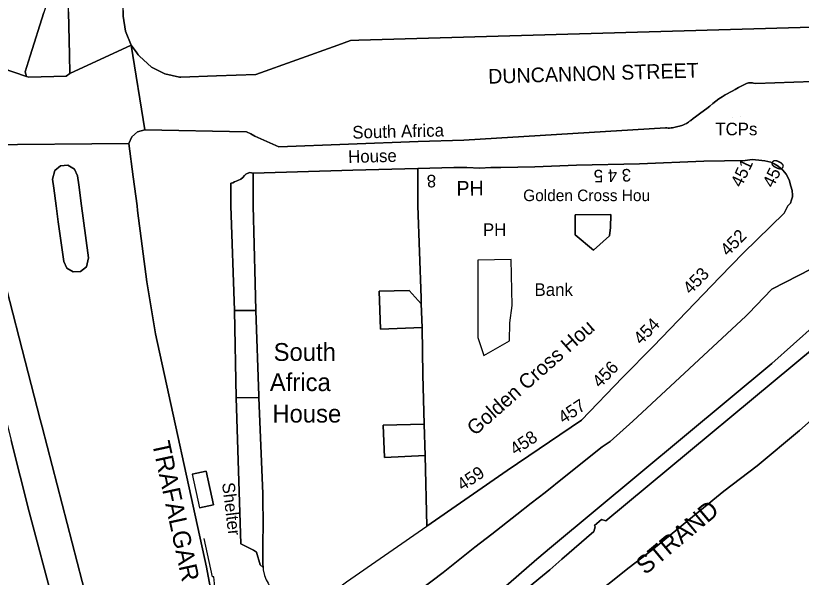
# Model space of a CAD drawing. Extents: x 529240 to 530363, y 179600 to 180767.
# Drawn here: x 530056.2 to 530149.8, y 180455.7 to 180522.7 of the extents above; entities that cross this region are included whole.
import ezdxf

# ---------------------------------------------------------------- set-up
doc = ezdxf.new("R2010")
doc.units = 0
for name, color, linetype in [('Building', 7, 'Continuous'), ('General surface', 7, 'Continuous'), ('Road Or Track', 7, 'Continuous'), ('Roadside', 7, 'Continuous'), ('Structure', 7, 'Continuous'), ('Unclassified', 7, 'Continuous')]:
    doc.layers.add(name, color=color, linetype=linetype)

msp = doc.modelspace()

# ---------------------------------------------------------------- linework, layer by layer
at = {"layer": 'Building'}
for points in [[(530105.2, 180461.8), (530114.8, 180468.45), (530123.65, 180474.45), (530128.55, 180479.5), (530132.25, 180483.25), (530140.15, 180491.5), (530142.95, 180494.4), (530147.8, 180499.1), (530148.25, 180500), (530148.55, 180500.3), (530148.7, 180500.7), (530148.8, 180501.05), (530148.8, 180501.25), (530148.75, 180501.8), (530148.6, 180502.35), (530148.4, 180503.1), (530148.05, 180503.75), (530147.65, 180504.25), (530147.1, 180504.7), (530146.6, 180505), (530146.2, 180505.2), (530145.5, 180505.35), (530144.8, 180505.45), (530144, 180505.5), (530143.15, 180505.4), (530138.25, 180505.3), (530130.55, 180505), (530123.05, 180504.85), (530118.1, 180504.65), (530114.05, 180504.55), (530112.85, 180504.55), (530111.55, 180504.5), (530110, 180504.55), (530108.45, 180504.55), (530104.15, 180504.45), (530104.15, 180500), (530104.55, 180489), (530104.55, 180488.3), (530104.65, 180485.5), (530104.75, 180479.85), (530104.9, 180473.95), (530105, 180470.2)], [(530125.1, 180494.7), (530127, 180496.4), (530127.1, 180497.4), (530127.15, 180498.95), (530122.9, 180498.9), (530122.9, 180496.55)], [(530112, 180482.15), (530115.05, 180483.9), (530115.1, 180486.05), (530115.4, 180488.1), (530115.25, 180493.6), (530111.3, 180493.5), (530111.3, 180484.3)], [(530082.3, 180487.5), (530082.5, 180477.1), (530085.2, 180477.15), (530085.2, 180477.35), (530084.85, 180487.5)], [(530078.11, 180463.98), (530079.77, 180464.34), (530078.9, 180468.34), (530077.24, 180467.98)]]:
    msp.add_lwpolyline(points, close=True, dxfattribs=at)
for points in [[(530104.15, 180504.45), (530108.45, 180504.55), (530110, 180504.55), (530111.55, 180504.5), (530112.85, 180504.55), (530114.05, 180504.55), (530118.1, 180504.65), (530123.05, 180504.85), (530130.55, 180505), (530138.25, 180505.3)], [(530138.25, 180505.3), (530143.15, 180505.4), (530144, 180505.5), (530144.8, 180505.45), (530145.5, 180505.35), (530146.2, 180505.2), (530146.6, 180505), (530147.1, 180504.7), (530147.65, 180504.25), (530148.05, 180503.75), (530148.4, 180503.1), (530148.6, 180502.35), (530148.75, 180501.8), (530148.8, 180501.25), (530148.8, 180501.05), (530148.7, 180500.7), (530148.55, 180500.3), (530148.25, 180500), (530147.8, 180499.1), (530142.95, 180494.4), (530140.15, 180491.5), (530132.25, 180483.25), (530128.55, 180479.5), (530123.65, 180474.45), (530114.8, 180468.45), (530105.2, 180461.8)], [(530095.65, 180455.15), (530105.2, 180461.8), (530105, 180470.2), (530100.15, 180470), (530100, 180473.85), (530104.9, 180473.95), (530104.75, 180479.85), (530104.65, 180485.5), (530099.7, 180485.3), (530099.55, 180489.8), (530103.1, 180489.9), (530104.55, 180488.3), (530104.55, 180489), (530104.15, 180500), (530104.15, 180504.45), (530096.4, 180504.25), (530084.5, 180503.9), (530084.5, 180500), (530084.75, 180490.75), (530084.85, 180487.5), (530085.2, 180477.35), (530085.2, 180477.15), (530085.65, 180465.65), (530085.7, 180461.5), (530085.65, 180460.25), (530085.65, 180457.3), (530085.7, 180456.85), (530085.7, 180456.6), (530085.85, 180455.9), (530086.05, 180455.4)], [(530084.5, 180503.9), (530096.4, 180504.25), (530104.15, 180504.45)], [(530104.15, 180504.45), (530104.15, 180500), (530104.55, 180489), (530104.55, 180488.3)], [(530084.85, 180487.5), (530084.75, 180490.75), (530084.5, 180500), (530084.5, 180503.9)], [(530127, 180496.4), (530125.1, 180494.7), (530122.9, 180496.55), (530122.9, 180498.9), (530127.15, 180498.95), (530127.1, 180497.4), (530127, 180496.4)], [(530112, 180482.15), (530115.05, 180483.9), (530115.1, 180486.05), (530115.4, 180488.1), (530115.25, 180493.6), (530111.3, 180493.5), (530111.3, 180484.3), (530112, 180482.15)], [(530104.65, 180485.5), (530099.7, 180485.3), (530099.55, 180489.8), (530103.1, 180489.9), (530104.55, 180488.3)], [(530084.85, 180487.5), (530085.2, 180477.35), (530085.2, 180477.15)], [(530104.55, 180488.3), (530104.65, 180485.5)], [(530104.65, 180485.5), (530104.75, 180479.85), (530104.9, 180473.95)], [(530085.2, 180477.15), (530085.65, 180465.65), (530085.7, 180461.5), (530085.65, 180460.25), (530085.65, 180457.3), (530085.7, 180456.85)], [(530105, 180470.2), (530100.15, 180470), (530100, 180473.85), (530104.9, 180473.95)], [(530104.9, 180473.95), (530105, 180470.2)], [(530105, 180470.2), (530105.2, 180461.8)], [(530085.7, 180456.85), (530085.7, 180456.6), (530085.85, 180455.9), (530086.05, 180455.4), (530086.3, 180455), (530086.45, 180454.65), (530086.75, 180454.2), (530087.25, 180453.6), (530087.65, 180453.25), (530088.05, 180453), (530088.45, 180452.8), (530088.8, 180452.65), (530089.05, 180452.65), (530089.45, 180452.45), (530090.2, 180452.55), (530090.95, 180452.7), (530092.15, 180453), (530092.7, 180453.15), (530093.3, 180453.4), (530095.65, 180455.15), (530105.2, 180461.8)]]:
    msp.add_lwpolyline(points, dxfattribs=at)
at = {"layer": 'General surface'}
for points in [[(530084.5, 180503.9), (530084.1, 180503.95), (530083.8, 180503.85), (530083.65, 180503.75), (530083.5, 180503.6), (530083.3, 180503.35), (530083.05, 180503.15), (530082.7, 180503), (530082.3, 180502.85), (530082.1, 180502.75), (530081.85, 180502.7), (530081.85, 180500), (530082.3, 180487.5), (530084.85, 180487.5), (530084.75, 180490.75), (530084.5, 180500)], [(530127, 180496.4), (530127.1, 180497.4), (530127.15, 180498.95), (530122.9, 180498.9), (530122.9, 180496.55), (530125.1, 180494.7)], [(530112, 180482.15), (530115.05, 180483.9), (530115.1, 180486.05), (530115.4, 180488.1), (530115.25, 180493.6), (530111.3, 180493.5), (530111.3, 180484.3)], [(530104.65, 180485.5), (530104.55, 180488.3), (530103.1, 180489.9), (530099.55, 180489.8), (530099.7, 180485.3)], [(530082.5, 180477.1), (530083.05, 180459.7), (530084.55, 180458.95), (530084.9, 180458.7), (530085.35, 180457.2), (530085.7, 180456.85), (530085.65, 180457.3), (530085.65, 180460.25), (530085.7, 180461.5), (530085.65, 180465.65), (530085.2, 180477.15)], [(530104.9, 180473.95), (530100, 180473.85), (530100.15, 180470), (530105, 180470.2)]]:
    msp.add_lwpolyline(points, close=True, dxfattribs=at)
msp.add_lwpolyline([(530060.7, 180452.6), (530057.8, 180463.5), (530055.65, 180472)], dxfattribs=at)
at = {"layer": 'Road Or Track'}
for points in [[(530069.97, 180519.15), (530069.29, 180520.82), (530069.03, 180522.59), (530069.01, 180523.29), (530068.01, 180558.74), (530068.48, 180559.06), (530070.58, 180559.07), (530070.57, 180570.77), (530067.21, 180570.76), (530066.84, 180570.93), (530065.39, 180579.19), (530063.66, 180587.1), (530063.26, 180588.57), (530062.26, 180592.29), (530061.55, 180594.92), (530058.96, 180602.86)], [(530062.67, 180515.77), (530062.62, 180518.01), (530062.5, 180523.11), (530062.44, 180525.64), (530062.25, 180526.2), (530061.78, 180526.56), (530061.19, 180526.59), (530060.69, 180526.27), (530060.49, 180525.92), (530059.57, 180523.04), (530057.93, 180517.89), (530057.32, 180515.98), (530057.48, 180515.43)], [(530053.15, 180516.9), (530057.48, 180515.43), (530057.32, 180515.98), (530057.93, 180517.89), (530059.57, 180523.04)], [(530062.5, 180523.11), (530062.62, 180518.01), (530062.67, 180515.77), (530069.97, 180519.15), (530069.29, 180520.82), (530069.03, 180522.59), (530069.01, 180523.29)], [(530174.99, 180522.51), (530174.16, 180522.33), (530173.08, 180522.14), (530172, 180522), (530169.9, 180522), (530169.13, 180521.97), (530151.1, 180521.3), (530097.11, 180519.73), (530096.11, 180519.69), (530094.62, 180519.16), (530084.85, 180515.65), (530080.13, 180515.48), (530075.9, 180515.34), (530075.74, 180515.33), (530073.99, 180515.73), (530072.39, 180516.54), (530070.95, 180517.85), (530070.8, 180518), (530070.64, 180518.22), (530070.43, 180518.52), (530069.97, 180519.15)], [(530151.1, 180521.3), (530097.11, 180519.73), (530096.11, 180519.69), (530094.62, 180519.16), (530084.85, 180515.65), (530080.13, 180515.48), (530075.9, 180515.34), (530075.74, 180515.33), (530073.99, 180515.73), (530072.39, 180516.54), (530070.95, 180517.85), (530070.8, 180518), (530070.64, 180518.22), (530070.43, 180518.52), (530069.97, 180519.15), (530071.6, 180509.06), (530083.71, 180508.81), (530084.24, 180508.57), (530084.71, 180508.31), (530087.59, 180507.02), (530104.2, 180507.65), (530109.61, 180507.83), (530133.65, 180509.29), (530133.81, 180509.28), (530133.98, 180509.27), (530134.15, 180509.27), (530134.32, 180509.28), (530134.49, 180509.3), (530134.65, 180509.32), (530134.82, 180509.35), (530134.99, 180509.39), (530135.15, 180509.43), (530135.32, 180509.48), (530135.74, 180509.62), (530135.95, 180509.71), (530136.15, 180509.81), (530136.29, 180509.89), (530136.42, 180509.98), (530136.54, 180510.07), (530136.67, 180510.16), (530136.95, 180510.39), (530137.24, 180510.61), (530137.89, 180511.07), (530138.6, 180511.59), (530138.95, 180511.89), (530139.3, 180512.18), (530139.66, 180512.47), (530140.02, 180512.75), (530140.4, 180513), (530140.79, 180513.24), (530141.59, 180513.66), (530141.98, 180513.88), (530142.38, 180514.08), (530143.33, 180514.57), (530143.44, 180514.61), (530143.56, 180514.64), (530143.8, 180514.66), (530144.04, 180514.64), (530144.17, 180514.62), (530144.41, 180514.58), (530155.75, 180514.98)], [(530057.48, 180515.43), (530057.79, 180515.32), (530062.21, 180515.44), (530062.67, 180515.77)], [(530071.6, 180509.06), (530083.71, 180508.81), (530084.24, 180508.57), (530084.71, 180508.31), (530087.59, 180507.02), (530104.2, 180507.65), (530109.61, 180507.83), (530133.65, 180509.29), (530133.81, 180509.28), (530133.98, 180509.27), (530134.15, 180509.27), (530134.32, 180509.28), (530134.49, 180509.3), (530134.65, 180509.32), (530134.82, 180509.35), (530134.99, 180509.39), (530135.15, 180509.43), (530135.32, 180509.48), (530135.74, 180509.62), (530135.95, 180509.71), (530136.15, 180509.81), (530136.29, 180509.89), (530136.42, 180509.98), (530136.54, 180510.07), (530136.67, 180510.16), (530136.95, 180510.39), (530137.24, 180510.61), (530137.89, 180511.07), (530138.6, 180511.59), (530138.95, 180511.89), (530139.3, 180512.18), (530139.66, 180512.47), (530140.02, 180512.75), (530140.4, 180513), (530140.79, 180513.24), (530141.59, 180513.66), (530141.98, 180513.88), (530142.38, 180514.08), (530143.33, 180514.57), (530143.44, 180514.61), (530143.56, 180514.64), (530143.8, 180514.66), (530144.04, 180514.64), (530144.17, 180514.62), (530144.41, 180514.58), (530155.75, 180514.98)], [(530069.71, 180507.41), (530070.06, 180508.23), (530070.73, 180508.82), (530071.6, 180509.06)], [(530051.99, 180507.26), (530052.2, 180503.06), (530052.52, 180500.9), (530052.66, 180500), (530052.83, 180498.91), (530053.34, 180496.94), (530059.14, 180474.5), (530059.37, 180473.63), (530065.32, 180450.57), (530067.12, 180442.36)], [(530081.21, 180444.77), (530078.95, 180456.89), (530072.89, 180484.71), (530071.85, 180490.92), (530070.74, 180499.45), (530070.67, 180500), (530070.22, 180503.44), (530069.71, 180507.41)], [(530064.06, 180500), (530063.72, 180502.51), (530063.58, 180503.57), (530063.21, 180504.37), (530062.44, 180504.82), (530061.56, 180504.77), (530060.86, 180504.22), (530060.61, 180503.16), (530060.75, 180502.08), (530061.03, 180500), (530061.29, 180498.08), (530061.93, 180493.37), (530062.3, 180492.57), (530063.06, 180492.12), (530063.95, 180492.17), (530064.65, 180492.72), (530064.9, 180493.78), (530064.26, 180498.51), (530064.06, 180500)], [(530143.57, 180487.15), (530146.34, 180490.05), (530152.63, 180493.29), (530158.87, 180500), (530163.56, 180505.05)], [(530083.71, 180426.65), (530083.76, 180426.7), (530083.81, 180426.75), (530083.86, 180426.8), (530083.91, 180426.84), (530083.96, 180426.89), (530084.02, 180426.93), (530090.91, 180434.02), (530103.62, 180445.06), (530118.34, 180457.85), (530120.09, 180459.31), (530146.35, 180481.2), (530151.51, 180485.78), (530157.33, 180491.64), (530165.15, 180500), (530166.31, 180501.24)], [(530168.55, 180499.29), (530168.43, 180498.73), (530158.53, 180489.31), (530154.01, 180485.26), (530126.57, 180462.42), (530126.03, 180462.58), (530125.18, 180461.87), (530125.27, 180461.71), (530125.12, 180461.17), (530121.3, 180457.85), (530119.86, 180456.6), (530109.76, 180448.27), (530104.69, 180443.73), (530093.17, 180432.51), (530088.24, 180426.97), (530085.64, 180424.05), (530085.52, 180424), (530085.46, 180423.98), (530085.39, 180423.96), (530085.32, 180423.95), (530085.25, 180423.94), (530085.18, 180423.93)], [(530152.63, 180493.29), (530146.34, 180490.05), (530143.57, 180487.15), (530143.24, 180486.84), (530129.75, 180474.3), (530127.05, 180471.9), (530126.1, 180471.25), (530121.6, 180467.65), (530119.3, 180465.8), (530117.65, 180464.55), (530115.95, 180463.2), (530112.95, 180460.85), (530110.95, 180459.3), (530107.15, 180456.25), (530101.6, 180452.05)], [(530149.65, 180473.2), (530152.75, 180475.95), (530158.85, 180481.15), (530169.19, 180489.41), (530169.51, 180489.68), (530169.81, 180489.96), (530170.12, 180490.24), (530170.42, 180490.52), (530171.04, 180491.08), (530171.36, 180491.34), (530171.6, 180491.55), (530171.68, 180491.63), (530171.92, 180491.84), (530172.1, 180491.96), (530172.19, 180492.01), (530172.28, 180492.05)], [(530143.57, 180487.15), (530143.24, 180486.84), (530129.75, 180474.3), (530127.05, 180471.9), (530126.1, 180471.25), (530121.6, 180467.65), (530119.3, 180465.8), (530117.65, 180464.55), (530115.95, 180463.2), (530112.95, 180460.85), (530110.95, 180459.3), (530107.15, 180456.25), (530101.6, 180452.05)], [(530103.62, 180445.06), (530118.34, 180457.85), (530120.09, 180459.31), (530146.35, 180481.2), (530151.51, 180485.78)], [(530154.01, 180485.26), (530126.57, 180462.42), (530126.03, 180462.58), (530125.18, 180461.87), (530125.27, 180461.71), (530125.12, 180461.17), (530121.3, 180457.85), (530119.86, 180456.6), (530109.76, 180448.27)], [(530124.45, 180452.95), (530129.35, 180456.85), (530132.05, 180458.95), (530140.6, 180465.95), (530144.6, 180469), (530149.65, 180473.2), (530152.75, 180475.95)], [(530149.65, 180473.2), (530144.6, 180469), (530140.6, 180465.95), (530132.05, 180458.95)], [(530132.05, 180458.95), (530129.35, 180456.85), (530124.45, 180452.95), (530123.65, 180452.3)]]:
    msp.add_lwpolyline(points, dxfattribs=at)
for points in [[(530053.15, 180516.9), (530052.82, 180515.6), (530052.19, 180511.45), (530051.99, 180507.26), (530069.71, 180507.41), (530070.06, 180508.23), (530070.73, 180508.82), (530071.6, 180509.06), (530069.97, 180519.15), (530062.67, 180515.77), (530062.21, 180515.44), (530057.79, 180515.32), (530057.48, 180515.43)], [(530069.71, 180507.41), (530051.99, 180507.26), (530052.2, 180503.06), (530052.52, 180500.9), (530052.66, 180500), (530052.83, 180498.91), (530053.34, 180496.94), (530059.14, 180474.5), (530059.37, 180473.63), (530065.32, 180450.57), (530067.12, 180442.36), (530073.34, 180443.66), (530073.49, 180444.3), (530073.94, 180444.68), (530074.52, 180444.75), (530075.05, 180444.48), (530075.32, 180443.94), (530081.21, 180444.77), (530078.95, 180456.89), (530072.89, 180484.71), (530071.85, 180490.92), (530070.74, 180499.45), (530070.67, 180500), (530070.22, 180503.44)], [(530064.06, 180500), (530064.26, 180498.51), (530064.9, 180493.78), (530064.65, 180492.72), (530063.95, 180492.17), (530063.06, 180492.12), (530062.3, 180492.57), (530061.93, 180493.37), (530061.29, 180498.08), (530061.03, 180500), (530060.75, 180502.08), (530060.61, 180503.16), (530060.86, 180504.22), (530061.56, 180504.77), (530062.44, 180504.82), (530063.21, 180504.37), (530063.58, 180503.57), (530063.72, 180502.51)]]:
    msp.add_lwpolyline(points, close=True, dxfattribs=at)
at = {"layer": 'Roadside'}
for points in [[(530057.48, 180515.43), (530057.79, 180515.32), (530062.21, 180515.44), (530062.67, 180515.77), (530062.62, 180518.01), (530062.5, 180523.11), (530062.44, 180525.64), (530062.25, 180526.2), (530061.78, 180526.56), (530061.19, 180526.59), (530060.69, 180526.27), (530060.49, 180525.92), (530059.57, 180523.04), (530057.93, 180517.89), (530057.32, 180515.98)], [(530064.06, 180500), (530063.72, 180502.51), (530063.58, 180503.57), (530063.21, 180504.37), (530062.44, 180504.82), (530061.56, 180504.77), (530060.86, 180504.22), (530060.61, 180503.16), (530060.75, 180502.08), (530061.03, 180500), (530061.29, 180498.08), (530061.93, 180493.37), (530062.3, 180492.57), (530063.06, 180492.12), (530063.95, 180492.17), (530064.65, 180492.72), (530064.9, 180493.78), (530064.26, 180498.51)], [(530078.11, 180463.98), (530079.77, 180464.34), (530078.9, 180468.34), (530077.24, 180467.98)]]:
    msp.add_lwpolyline(points, close=True, dxfattribs=at)
for points in [[(530069.01, 180523.29), (530069.03, 180522.59), (530069.29, 180520.82), (530069.97, 180519.15), (530070.43, 180518.52), (530070.64, 180518.22), (530070.8, 180518), (530070.95, 180517.85), (530072.39, 180516.54), (530073.99, 180515.73), (530075.74, 180515.33), (530075.9, 180515.34), (530080.13, 180515.48), (530084.85, 180515.65), (530094.62, 180519.16), (530096.11, 180519.69), (530097.11, 180519.73), (530151.1, 180521.3)], [(530155.75, 180514.98), (530144.41, 180514.58), (530144.17, 180514.62), (530144.04, 180514.64), (530143.8, 180514.66), (530143.56, 180514.64), (530143.44, 180514.61), (530143.33, 180514.57), (530142.38, 180514.08), (530141.98, 180513.88), (530141.59, 180513.66), (530140.79, 180513.24), (530140.4, 180513), (530140.02, 180512.75), (530139.66, 180512.47), (530139.3, 180512.18), (530138.95, 180511.89), (530138.6, 180511.59), (530137.89, 180511.07), (530137.24, 180510.61), (530136.95, 180510.39), (530136.67, 180510.16), (530136.54, 180510.07), (530136.42, 180509.98), (530136.29, 180509.89), (530136.15, 180509.81), (530135.95, 180509.71), (530135.74, 180509.62), (530135.32, 180509.48), (530135.15, 180509.43), (530134.99, 180509.39), (530134.82, 180509.35), (530134.65, 180509.32), (530134.49, 180509.3), (530134.32, 180509.28), (530134.15, 180509.27), (530133.98, 180509.27), (530133.81, 180509.28), (530133.65, 180509.29), (530109.61, 180507.83), (530104.2, 180507.65), (530087.59, 180507.02), (530084.71, 180508.31), (530084.24, 180508.57), (530083.71, 180508.81), (530071.6, 180509.06), (530070.73, 180508.82), (530070.06, 180508.23), (530069.71, 180507.41), (530070.22, 180503.44), (530070.67, 180500), (530070.74, 180499.45), (530071.85, 180490.92), (530072.89, 180484.71), (530078.95, 180456.89), (530081.21, 180444.77)], [(530095.65, 180455.15), (530105.2, 180461.8), (530114.8, 180468.45), (530123.65, 180474.45), (530128.55, 180479.5), (530132.25, 180483.25), (530140.15, 180491.5), (530142.95, 180494.4), (530147.8, 180499.1), (530148.25, 180500), (530148.55, 180500.3), (530148.7, 180500.7), (530148.8, 180501.05), (530148.8, 180501.25), (530148.75, 180501.8), (530148.6, 180502.35), (530148.4, 180503.1), (530148.05, 180503.75), (530147.65, 180504.25), (530147.1, 180504.7), (530146.6, 180505), (530146.2, 180505.2), (530145.5, 180505.35), (530144.8, 180505.45), (530144, 180505.5), (530143.15, 180505.4), (530138.25, 180505.3), (530130.55, 180505), (530123.05, 180504.85), (530118.1, 180504.65), (530114.05, 180504.55), (530112.85, 180504.55), (530111.55, 180504.5), (530110, 180504.55), (530108.45, 180504.55), (530104.15, 180504.45), (530096.4, 180504.25), (530084.5, 180503.9), (530084.1, 180503.95), (530083.8, 180503.85), (530083.65, 180503.75), (530083.5, 180503.6), (530083.3, 180503.35), (530083.05, 180503.15), (530082.7, 180503), (530082.3, 180502.85), (530082.1, 180502.75), (530081.85, 180502.7), (530081.85, 180500), (530082.3, 180487.5), (530082.5, 180477.1), (530083.05, 180459.7), (530084.55, 180458.95), (530084.9, 180458.7), (530085.35, 180457.2), (530085.7, 180456.85), (530085.7, 180456.6), (530085.85, 180455.9), (530086.05, 180455.4)], [(530054.52, 180416.29), (530061, 180421.48), (530063.69, 180423.81), (530065.34, 180425.55), (530066.66, 180427.56), (530067.59, 180429.76), (530068.13, 180432.1), (530068.24, 180434.49), (530068.09, 180435.55), (530067.39, 180440.47), (530067.12, 180442.36), (530065.32, 180450.57), (530059.37, 180473.63), (530059.14, 180474.5), (530053.34, 180496.94)], [(530101.6, 180452.05), (530107.15, 180456.25), (530110.95, 180459.3), (530112.95, 180460.85), (530115.95, 180463.2), (530117.65, 180464.55), (530119.3, 180465.8), (530121.6, 180467.65), (530126.1, 180471.25), (530127.05, 180471.9), (530129.75, 180474.3), (530143.24, 180486.84), (530143.57, 180487.15), (530146.34, 180490.05), (530152.63, 180493.29)], [(530151.51, 180485.78), (530146.35, 180481.2), (530120.09, 180459.31), (530118.34, 180457.85), (530103.62, 180445.06)], [(530109.76, 180448.27), (530119.86, 180456.6), (530121.3, 180457.85), (530125.12, 180461.17), (530125.27, 180461.71), (530125.18, 180461.87), (530126.03, 180462.58), (530126.57, 180462.42), (530154.01, 180485.26)], [(530152.75, 180475.95), (530149.65, 180473.2), (530144.6, 180469), (530140.6, 180465.95), (530132.05, 180458.95), (530129.35, 180456.85), (530124.45, 180452.95), (530123.65, 180452.3), (530118.95, 180448.4), (530114.75, 180444.65), (530111.45, 180441.9), (530105.65, 180436), (530101.55, 180431.65), (530097.08, 180426.75), (530096.27, 180425.93), (530092.65, 180422.27), (530091.59, 180421.2), (530087.72, 180417.02), (530084.15, 180412.58), (530080.91, 180407.89), (530076.79, 180400.63), (530076, 180398.36), (530075.64, 180395.99)], [(530055.65, 180472), (530057.8, 180463.5), (530060.7, 180452.6)]]:
    msp.add_lwpolyline(points, dxfattribs=at)
at = {"layer": 'Structure'}
for p, q in [((530141.6, 180510.55), (530141.6, 180510.55)), ((530142.6, 180510.6), (530142.6, 180510.6))]:
    msp.add_line(p, q, dxfattribs=at)
at = {"layer": 'Unclassified'}
for points in [[(530069.97, 180519.15), (530062.67, 180515.77)], [(530071.6, 180509.06), (530069.97, 180519.15)], [(530057.48, 180515.43), (530053.15, 180516.9)], [(530069.71, 180507.41), (530051.99, 180507.26)], [(530082.3, 180487.5), (530081.85, 180500), (530081.85, 180502.7), (530082.1, 180502.75), (530082.3, 180502.85), (530082.7, 180503), (530083.05, 180503.15), (530083.3, 180503.35), (530083.5, 180503.6), (530083.65, 180503.75), (530083.8, 180503.85), (530084.1, 180503.95), (530084.5, 180503.9)], [(530051.55, 180488.2), (530053.75, 180479.6), (530055.65, 180472), (530057.8, 180463.5), (530060.7, 180452.6), (530062.5, 180445.35)], [(530082.3, 180487.5), (530084.85, 180487.5)], [(530082.5, 180477.1), (530082.3, 180487.5)], [(530085.2, 180477.15), (530082.5, 180477.1)], [(530085.7, 180456.85), (530085.35, 180457.2), (530084.9, 180458.7), (530084.55, 180458.95), (530083.05, 180459.7), (530082.5, 180477.1)], [(530077.24, 180467.98), (530078.9, 180468.34), (530079.77, 180464.34), (530078.11, 180463.98)], [(530077.24, 180467.98), (530078.11, 180463.98)], [(530079.96, 180454.55), (530079.81, 180455.74), (530079.66, 180455.74), (530078.66, 180460.31)]]:
    msp.add_lwpolyline(points, dxfattribs=at)

# ---------------------------------------------------------------- texts
at = {"layer": 'Road Or Track'}
for s, height, rotation, p in [('DUNCANNON STREET', 1.75, 1.7, (530112.55, 180514.55)), ('TRAFALGAR SQUARE', 2.125, 282.2, (530072.46, 180471.7)), ('STRAND', 2.125, 40, (530131.26, 180455.91))]:
    msp.add_text(s, height=height, rotation=rotation, dxfattribs=at).set_placement(p)
at = {"layer": 'Structure'}
msp.add_text('TCPs', height=1.5, dxfattribs=at).set_placement((530139.6, 180508.4))
msp.add_text('Shelter', height=1.5, rotation=276.9, dxfattribs=at).set_placement((530080.8, 180466.92))
at = {"layer": 'Unclassified'}
for s, height, rotation, p in [('South Africa', 1.5, 1.4, (530096.35, 180508)), ('House', 1.5, 1.4, (530095.85, 180505.1)), ('451', 1.5, 64.4, (530142.7, 180502.1)), ('450', 1.5, 64.4, (530146.5, 180502.05)), ('3 4 5', 1.5, 181.6, (530129.55, 180504.4)), ('8', 1.5, 181.8, (530106.3, 180503.7)), ('PH', 1.75, 0.5, (530108.75, 180501.2)), ('452', 1.5, 45.5, (530141.1, 180493.9)), ('453', 1.5, 45.9, (530136.65, 180489.35)), ('454', 1.5, 45.5, (530130.75, 180483.35)), ('Golden Cross Hou', 1.75, 41.5, (530110.95, 180472.5)), ('456', 1.5, 46, (530125.85, 180478.2)), ('457', 1.5, 33.4, (530121.5, 180473.95)), ('458', 1.5, 33.3, (530115.75, 180470.2)), ('459', 1.5, 33.6, (530109.45, 180465.95))]:
    msp.add_text(s, height=height, rotation=rotation, dxfattribs=at).set_placement(p)
for s, height, p in [('Golden Cross Hou', 1.375, (530116.7, 180500.55)), ('PH', 1.5, (530111.9, 180496.4)), ('Bank', 1.5, (530118.05, 180489.25)), ('South', 2.125, (530086.95, 180481.5)), ('Africa', 2.125, (530086.5, 180477.9)), ('House', 2.125, (530086.8, 180474.15))]:
    msp.add_text(s, height=height, dxfattribs=at).set_placement(p)

doc.saveas('drawing.dxf')
